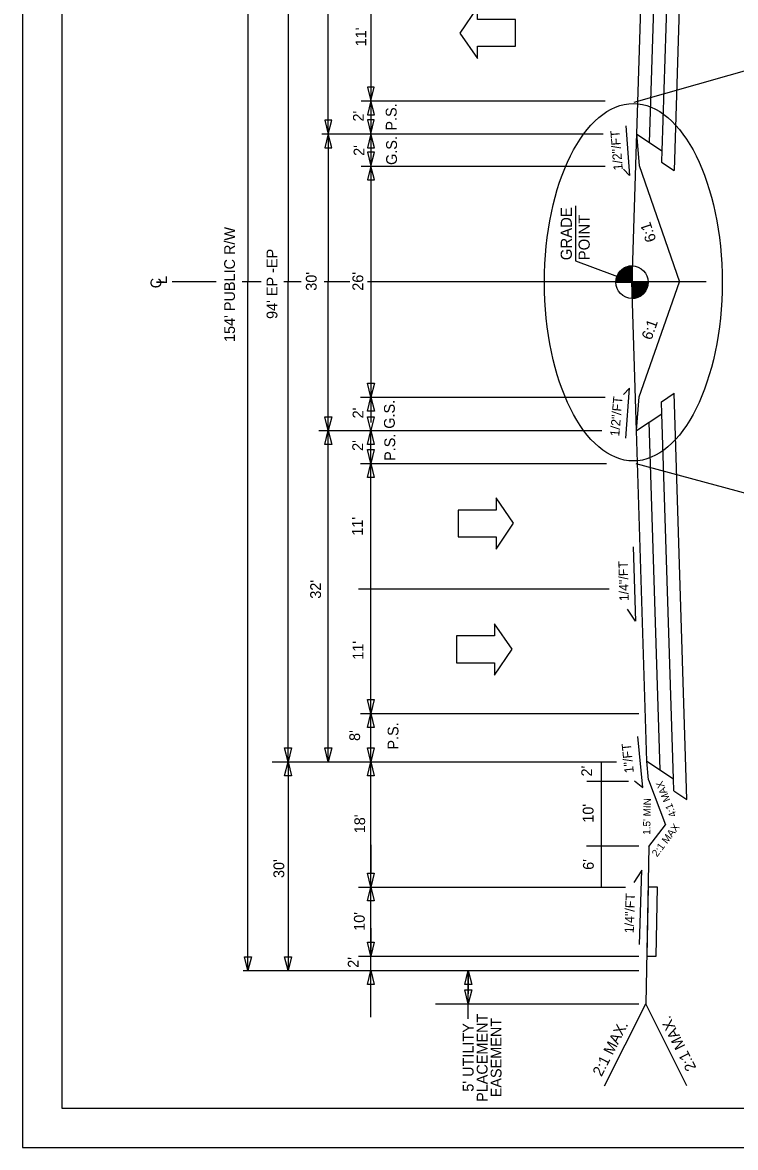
# Model space of a CAD drawing. Extents: x 0 to 8.5, y 0 to 11.
# Drawn here: x 0 to 4.53, y 0 to 7.15 of the extents above; entities that cross this region are included whole.
import ezdxf

# ---------------------------------------------------------------- set-up
doc = ezdxf.new("R2010")
doc.units = 0
for name, color, linetype in [('DIM', 7, 'Continuous'), ('GROUND', 7, 'Continuous'), ('INSET', 7, 'Continuous'), ('PROP LANE ARROW CELL', 7, 'Continuous'), ('ROAD SECTION', 7, 'Continuous'), ('SHEET BORDER', 7, 'Continuous'), ('SHEET TRIM BORDER', 7, 'Continuous'), ('SIDEWALK', 7, 'Continuous'), ('Typical Grade Point Symbol CELL', 7, 'Continuous')]:
    doc.layers.add(name, color=color, linetype=linetype)

msp = doc.modelspace()

# ---------------------------------------------------------------- linework, layer by layer
at = {"layer": 'DIM'}
for p, q in [((1.4336, 9.8715), (1.4335, 5.4978)), ((1.6884, 8.5451), (1.6883, 5.4977)), ((1.9442, 6.4405), (1.9442, 8.5451)), ((2.215, 7.4051), (2.2149, 6.4404)), ((2.1542, 6.65), (3.7048, 6.65)), ((1.9038, 6.4405), (3.6922, 6.4404)), ((1.944, 6.4404), (1.944, 5.4977)), ((2.2154, 6.4404), (2.2153, 4.6059)), ((2.1542, 6.2356), (3.7048, 6.2355)), ((3.516, 5.9831), (3.516, 5.6347)), ((3.516, 5.6347), (3.8744, 5.5)), ((1.2318, 5.5), (0.9514, 5.5)), ((1.5185, 5.5), (1.396, 5.5)), ((1.4336, 1.1241), (1.4335, 5.4978)), ((1.7722, 5.5), (1.6627, 5.5)), ((1.6884, 2.4504), (1.6883, 5.4977)), ((2.0807, 5.5), (1.9187, 5.5)), ((1.944, 4.5551), (1.944, 5.4977)), ((4.3475, 5.5), (2.1931, 5.5)), ((2.1488, 4.7672), (3.7048, 4.7671)), ((1.8833, 4.5551), (3.6845, 4.555)), ((1.9441, 2.4504), (1.944, 4.5551)), ((2.215, 3.5905), (2.2149, 4.5551)), ((2.1488, 4.3462), (3.7131, 4.3462)), ((3.8831, 3.8155), (3.8974, 3.3436)), ((2.215, 2.4504), (2.215, 3.5904)), ((2.1372, 3.5499), (3.7309, 3.5498)), ((3.8974, 3.3436), (3.8463, 3.4212)), ((2.1488, 2.7577), (3.919, 2.7577)), ((1.5865, 2.4504), (3.7764, 2.4504)), ((1.6884, 2.4504), (1.6884, 1.124)), ((2.215, 1.9133), (2.215, 2.4504)), ((3.6815, 1.6547), (3.6815, 2.4504)), ((3.5882, 2.3269), (3.8533, 2.3269)), ((2.215, 1.9223), (2.215, 1.746)), ((2.2151, 1.2117), (2.215, 1.9133)), ((3.5859, 1.9171), (3.919, 1.9171)), ((2.215, 1.5696), (2.215, 1.746)), ((3.9371, 1.7624), (3.8861, 1.6847)), ((3.9228, 1.2905), (3.9371, 1.7624)), ((2.1368, 1.6547), (3.834, 1.6547)), ((2.215, 1.3932), (2.2151, 1.2159)), ((2.1368, 1.2162), (3.9178, 1.2163)), ((2.2151, 1.124), (2.2151, 1.2159)), ((2.2151, 1.124), (2.2151, 1.2117)), ((1.4022, 1.1241), (3.9178, 1.124)), ((2.2151, 0.8284), (2.2151, 1.124)), ((2.8346, 1.124), (2.8346, 0.9755)), ((2.8346, 0.8952), (2.8346, 1.124)), ((2.8346, 0.8182), (2.8346, 0.9765)), ((2.6269, 0.9138), (3.9178, 0.9138))]:
    msp.add_line(p, q, dxfattribs=at)
for points in [[(2.1929, 6.7382), (2.2149, 6.65), (2.237, 6.7382)], [(2.2374, 6.5618), (2.2154, 6.65), (2.1933, 6.5618)], [(1.9226, 6.5277), (1.9446, 6.4395), (1.9667, 6.5277)], [(2.1929, 6.5286), (2.2149, 6.4404), (2.237, 6.5286)], [(1.9661, 6.3523), (1.944, 6.4404), (1.922, 6.3523)], [(2.2374, 6.3519), (2.2154, 6.4401), (2.1933, 6.3519)], [(2.1933, 6.3238), (2.2154, 6.2356), (2.2374, 6.3238)], [(2.2374, 6.1474), (2.2154, 6.2356), (2.1933, 6.1474)], [(2.2374, 4.8554), (2.2153, 4.7672), (2.1933, 4.8554)], [(2.1933, 4.679), (2.2153, 4.7672), (2.2374, 4.679)], [(1.9661, 4.6433), (1.944, 4.5551), (1.922, 4.6433)], [(2.237, 4.6433), (2.2149, 4.5551), (2.1929, 4.6433)], [(1.922, 4.4669), (1.944, 4.5551), (1.9661, 4.4669)], [(2.1929, 4.4669), (2.2149, 4.5551), (2.237, 4.4669)], [(2.237, 4.4344), (2.2149, 4.3462), (2.1929, 4.4344)], [(2.1929, 4.2581), (2.2149, 4.3462), (2.237, 4.2581)], [(2.237, 2.8459), (2.215, 2.7577), (2.1929, 2.8459)], [(2.193, 2.6696), (2.215, 2.7577), (2.237, 2.6696)], [(1.7105, 2.5386), (1.6884, 2.4504), (1.6664, 2.5386)], [(1.9661, 2.5386), (1.9441, 2.4504), (1.922, 2.5386)], [(2.2371, 2.5386), (2.215, 2.4504), (2.193, 2.5386)], [(1.6664, 2.3622), (1.6884, 2.4504), (1.7105, 2.3622)], [(2.193, 2.3622), (2.215, 2.4504), (2.2371, 2.3622)], [(2.2371, 1.7429), (2.215, 1.6547), (2.193, 1.7429)], [(2.193, 1.5665), (2.215, 1.6547), (2.2371, 1.5665)], [(2.2371, 1.304), (2.2151, 1.2159), (2.193, 1.304)], [(1.4557, 1.2122), (1.4336, 1.1241), (1.4116, 1.2122)], [(1.7105, 1.2122), (1.6884, 1.124), (1.6664, 1.2122)], [(2.193, 1.0358), (2.2151, 1.124), (2.2371, 1.0358)], [(2.8125, 1.0358), (2.8346, 1.124), (2.8566, 1.0358)], [(2.8566, 1.002), (2.8346, 0.9138), (2.8125, 1.002)]]:
    msp.add_lwpolyline(points, close=True, dxfattribs=at)
for points in [[(3.8361, 6.4924), (3.859, 6.1762), (3.8216, 6.2157)], [(3.8361, 4.5076), (3.859, 4.8238), (3.8216, 4.7842)], [(3.8905, 2.3306), (3.9452, 2.2866), (3.9119, 2.6112)]]:
    msp.add_lwpolyline(points, dxfattribs=at)
at = {"layer": 'GROUND'}
for p in [(3.9041, 6.445), (3.9041, 4.555)]:
    msp.add_line(p, (3.8744, 5.5), dxfattribs=at)
at = {"layer": 'INSET'}
for p, q in [((3.8898, 6.6428), (5.2813, 7.0385)), ((5.2555, 3.9782), (3.9012, 4.3437)), ((4.0369, 1.6547), (3.9778, 1.6547))]:
    msp.add_line(p, q, dxfattribs=at)
msp.add_ellipse((3.8835, 5.4977), major_axis=(0, -1.1355), ratio=0.49766, dxfattribs=at)
at = {"layer": 'PROP LANE ARROW CELL'}
for points in [[(2.8923, 6.9191), (2.8923, 6.9967), (3.1338, 6.9967), (3.1338, 7.1675), (2.8923, 7.1675), (2.8923, 7.2451), (2.7812, 7.0805), (2.8923, 6.9191)], [(3.0118, 4.1281), (3.0118, 4.0505), (2.7704, 4.0505), (2.7704, 3.8798), (3.0118, 3.8798), (3.0118, 3.8022), (3.123, 3.9667), (3.0118, 4.1281)], [(3.0018, 3.328), (3.0018, 3.2504), (2.7604, 3.2504), (2.7604, 3.0797), (3.0018, 3.0797), (3.0018, 3.0021), (3.1129, 3.1666), (3.0018, 3.328)]]:
    msp.add_lwpolyline(points, dxfattribs=at)
at = {"layer": 'ROAD SECTION'}
for p, q in [((4.2249, 8.7898), (4.1437, 6.2074)), ((4.1384, 8.6528), (4.0654, 6.3329)), ((4.0543, 8.5968), (3.9848, 6.3866)), ((3.9702, 8.5409), (3.9041, 6.4404)), ((3.9041, 6.4404), (4.0654, 6.3329)), ((3.9041, 6.4404), (3.9212, 6.2394)), ((4.0654, 6.3375), (4.063, 6.2612)), ((3.9212, 6.2394), (4.1776, 5.5)), ((4.063, 6.2612), (4.1437, 6.2074)), ((3.9216, 4.7687), (4.1776, 5.5)), ((4.063, 4.7388), (4.1437, 4.7926)), ((4.2249, 2.2102), (4.1437, 4.7926)), ((3.9041, 4.555), (3.9216, 4.7687)), ((4.0654, 4.6625), (4.063, 4.7388)), ((3.9041, 4.555), (4.0654, 4.6625)), ((4.1384, 2.3425), (4.0654, 4.6625)), ((4.0543, 2.3986), (3.9848, 4.6087)), ((3.9702, 2.4547), (3.9041, 4.555)), ((3.9702, 2.4547), (4.1384, 2.3425)), ((3.9811, 2.3358), (4.0879, 2.0512)), ((4.1408, 2.2662), (4.1384, 2.3425)), ((4.1408, 2.2662), (4.2249, 2.2102)), ((3.9832, 1.9116), (4.0879, 2.0512)), ((3.9832, 1.9116), (3.9625, 0.9138)), ((3.7014, 0.3917), (3.9625, 0.9138)), ((4.2232, 0.3924), (3.9625, 0.9138))]:
    msp.add_line(p, q, dxfattribs=at)
msp.add_lwpolyline([(3.9811, 2.3358), (3.9702, 2.4547)], dxfattribs=at)
at = {"layer": 'SHEET BORDER'}
msp.add_lwpolyline([(8.25, 10.75), (0.25, 10.75), (0.25, 0.25), (8.25, 0.25)], close=True, dxfattribs=at)
at = {"layer": 'SHEET TRIM BORDER'}
msp.add_lwpolyline([(8.5, 11), (0, 11), (0, 0), (8.5, 0)], close=True, dxfattribs=at)
at = {"layer": 'SIDEWALK'}
msp.add_lwpolyline([(3.9778, 1.6547), (3.9687, 1.2163), (4.0284, 1.2163), (4.0369, 1.6547)], close=True, dxfattribs=at)
at = {"layer": 'Typical Grade Point Symbol CELL'}
for p, q in [((3.8755, 5.6012), (3.8755, 5.4983)), ((3.8755, 5.4983), (3.7726, 5.4983)), ((3.9784, 5.498), (3.8755, 5.4983)), ((3.8755, 5.3953), (3.8755, 5.4983)), ((3.8755, 5.4983), (3.9784, 5.498))]:
    msp.add_line(p, q, dxfattribs=at)
for points in [[(3.8099, 5.5774), (3.8755, 5.5774)], [(3.8124, 5.5795), (3.8755, 5.5795)], [(3.8151, 5.5815), (3.8755, 5.5815)], [(3.8181, 5.5836), (3.8755, 5.5836)], [(3.8213, 5.5856), (3.8755, 5.5856)], [(3.8247, 5.5877), (3.8755, 5.5877)], [(3.8284, 5.5897), (3.8755, 5.5897)], [(3.8328, 5.5918), (3.8755, 5.5918)], [(3.8376, 5.5939), (3.8755, 5.5939)], [(3.8433, 5.5959), (3.8755, 5.5959)], [(3.8504, 5.598), (3.8755, 5.598)], [(3.8609, 5.6), (3.8755, 5.6)], [(3.7728, 5.5054), (3.8755, 5.5053)], [(3.7731, 5.5074), (3.8755, 5.5074)], [(3.7733, 5.5095), (3.8755, 5.5095)], [(3.7735, 5.5115), (3.8755, 5.5115)], [(3.7737, 5.5136), (3.8755, 5.5136)], [(3.774, 5.5156), (3.8755, 5.5156)], [(3.7744, 5.5177), (3.8755, 5.5177)], [(3.7749, 5.5198), (3.8755, 5.5198)], [(3.7754, 5.5218), (3.8755, 5.5218)], [(3.7758, 5.5239), (3.8755, 5.5239)], [(3.7765, 5.5259), (3.8755, 5.5259)], [(3.777, 5.528), (3.8755, 5.528)], [(3.7776, 5.5301), (3.8755, 5.5301)], [(3.7783, 5.5321), (3.8755, 5.5321)], [(3.779, 5.5342), (3.8755, 5.5342)], [(3.7799, 5.5362), (3.8755, 5.5362)], [(3.7808, 5.5383), (3.8755, 5.5383)], [(3.7818, 5.5404), (3.8755, 5.5403)], [(3.7827, 5.5424), (3.8755, 5.5424)], [(3.7836, 5.5445), (3.8755, 5.5445)], [(3.7847, 5.5465), (3.8755, 5.5465)], [(3.7859, 5.5486), (3.8755, 5.5486)], [(3.787, 5.5506), (3.8755, 5.5506)], [(3.7882, 5.5527), (3.8755, 5.5527)], [(3.7895, 5.5548), (3.8755, 5.5548)], [(3.7909, 5.5568), (3.8755, 5.5568)], [(3.7925, 5.5589), (3.8755, 5.5589)], [(3.7939, 5.5609), (3.8755, 5.5609)], [(3.7955, 5.563), (3.8755, 5.563)], [(3.7973, 5.5651), (3.8755, 5.5651)], [(3.7991, 5.5671), (3.8755, 5.5671)], [(3.801, 5.5692), (3.8755, 5.5692)], [(3.803, 5.5712), (3.8755, 5.5712)], [(3.8051, 5.5733), (3.8755, 5.5733)], [(3.8074, 5.5753), (3.8755, 5.5753)], [(3.7726, 5.5012), (3.8755, 5.5012)], [(3.7726, 5.4992), (3.7726, 5.4992), (3.8755, 5.4992)], [(3.7728, 5.5033), (3.8755, 5.5033)], [(3.8755, 5.4967), (3.9784, 5.4967), (3.9784, 5.4967)], [(3.8755, 5.4946), (3.9784, 5.4946)], [(3.8755, 5.4925), (3.9782, 5.4925)], [(3.8755, 5.4905), (3.9782, 5.4905)], [(3.8755, 5.4884), (3.978, 5.4884)], [(3.8755, 5.4864), (3.9777, 5.4864)], [(3.8755, 5.4843), (3.9775, 5.4843)], [(3.8755, 5.4823), (3.9771, 5.4822)], [(3.8755, 5.4802), (3.9768, 5.4802)], [(3.8755, 5.4781), (3.9764, 5.4781)], [(3.8755, 5.4761), (3.9759, 5.4761)], [(3.8755, 5.474), (3.9755, 5.474)], [(3.8755, 5.472), (3.975, 5.472)], [(3.8755, 5.4699), (3.9743, 5.4699)], [(3.8755, 5.4678), (3.9739, 5.4678)], [(3.8755, 5.4658), (3.9732, 5.4658)], [(3.8755, 5.4637), (3.9725, 5.4637)], [(3.8755, 5.4617), (3.9718, 5.4617)], [(3.8755, 5.4596), (3.9709, 5.4596)], [(3.8755, 5.4576), (3.97, 5.4576)], [(3.8755, 5.4555), (3.9691, 5.4555)], [(3.8755, 5.4534), (3.9681, 5.4534)], [(3.8755, 5.4514), (3.9672, 5.4514)], [(3.8755, 5.4493), (3.9661, 5.4493)], [(3.8755, 5.4473), (3.9649, 5.4473)], [(3.8755, 5.4452), (3.9638, 5.4452)], [(3.8755, 5.4431), (3.9624, 5.4431)], [(3.8755, 5.4411), (3.9611, 5.4411)], [(3.8755, 5.439), (3.9597, 5.439)], [(3.8755, 5.437), (3.9583, 5.437)], [(3.8755, 5.4349), (3.9567, 5.4349)], [(3.8755, 5.4329), (3.9551, 5.4329)], [(3.8755, 5.4308), (3.9533, 5.4308)], [(3.8755, 5.4287), (3.9515, 5.4287)], [(3.8755, 5.4267), (3.9496, 5.4267)], [(3.8755, 5.4246), (3.9476, 5.4246)], [(3.8755, 5.4226), (3.9453, 5.4226)], [(3.8755, 5.4205), (3.943, 5.4205)], [(3.8755, 5.4184), (3.9405, 5.4184)], [(3.8755, 5.4164), (3.938, 5.4164)], [(3.8755, 5.4143), (3.9352, 5.4143)], [(3.8755, 5.4123), (3.9322, 5.4123)], [(3.8755, 5.4102), (3.929, 5.4102)], [(3.8755, 5.4082), (3.9254, 5.4082)], [(3.8755, 5.4061), (3.9215, 5.4061)], [(3.8755, 5.404), (3.9171, 5.404)], [(3.8755, 5.402), (3.9123, 5.402)], [(3.8755, 5.3999), (3.9062, 5.3999)], [(3.8755, 5.3979), (3.8988, 5.3979)], [(3.8755, 5.3958), (3.8867, 5.3958)]]:
    msp.add_lwpolyline(points, dxfattribs=at)
msp.add_circle((3.8755, 5.4981), 0.1029, dxfattribs=at)
for start, end in [(89.98837, 179.98837), (269.98837, 359.98837)]:
    msp.add_arc((3.8755, 5.4981), 0.1029, start, end, dxfattribs=at)

# ---------------------------------------------------------------- texts
at = {"layer": 'DIM'}
for s, height, rotation, p in [("11'", 0.0686, 90.00211, (2.186, 6.9966)), ("2'", 0.0686, 90.00211, (2.1703, 6.5187)), ('P.S.', 0.0686, 90, (2.3787, 6.4611)), ('1/2"/FT', 0.0588, 94.71884, (3.817, 6.2109)), ("2'", 0.0686, 89.99789, (2.1739, 6.3006)), ('G.S.', 0.0686, 90, (2.3809, 6.2428)), ('GRADE', 0.0709, 89.99789, (3.493, 5.6375)), ('POINT', 0.0709, 89.99789, (3.6066, 5.637)), ('6:1', 0.0686, 108.78222, (4.0312, 5.7658)), ("154' PUBLIC R/W", 0.0686, 90.00211, (1.3511, 5.1178)), ("94' EP -EP", 0.0686, 89.99789, (1.6209, 5.2643)), ('C', 0.0686, 89.99789, (0.8827, 5.4593)), ('L', 0.0686, 89.94479, (0.9187, 5.4863)), ("30'", 0.0686, 89.99789, (1.8704, 5.4436)), ("26'", 0.0686, 89.99789, (2.1665, 5.4436)), ('6:1', 0.0686, 70.47313, (3.9986, 5.1261)), ('G.S.', 0.0686, 90, (2.3672, 4.567)), ('1/2"/FT', 0.0588, 85.28116, (3.7944, 4.5162)), ("2'", 0.0686, 89.99789, (2.1675, 4.6324)), ('P.S.', 0.0686, 90, (2.3697, 4.3623)), ("2'", 0.0686, 90.00211, (2.1654, 4.4261)), ("11'", 0.0686, 90.00211, (2.1643, 3.8871)), ('1/4"/FT', 0.0588, 91.7366, (3.855, 3.4719)), ("32'", 0.0686, 90.00211, (1.8978, 3.4868)), ("11'", 0.0686, 90.00211, (2.1679, 3.099)), ("8'", 0.0686, 90.00211, (2.1465, 2.5833)), ('P.S.', 0.0686, 90, (2.3904, 2.5283)), ('1"/FT', 0.0588, 95.96017, (3.8873, 2.382)), ("2'", 0.0686, 90.00211, (3.6217, 2.3574)), ('4:1 MAX', 0.04704, 112.20097, (4.1602, 2.11)), ("10'", 0.0686, 90.00211, (3.631, 2.0636)), ("1.5' MIN", 0.04704, 88.85215, (3.9913, 1.9867)), ("18'", 0.0686, 90.00211, (2.1785, 1.9966)), ('2:1 MAX', 0.04704, 52.92086, (4.0346, 1.8427)), ("30'", 0.0686, 90, (1.6643, 1.7121)), ("6'", 0.0686, 90.00211, (3.6323, 1.7642)), ('1/4"/FT', 0.0588, 88.2634, (3.8864, 1.3604)), ("10'", 0.0686, 89.99789, (2.176, 1.3766)), ("2'", 0.0686, 90.00211, (2.1372, 1.1417)), ("5' UTILITY", 0.0686, 90, (2.8681, 0.3545)), ('PLACEMENT', 0.0686, 90, (2.9568, 0.2896)), ('EASEMENT', 0.0686, 90, (3.0456, 0.3189)), ('2:1 MAX.', 0.0686, 62.953, (3.6817, 0.4464)), ('2:1 MAX.', 0.0686, 117.047, (4.2857, 0.5067))]:
    msp.add_text(s, height=height, rotation=rotation, dxfattribs=at).set_placement(p)

doc.saveas('drawing.dxf')
